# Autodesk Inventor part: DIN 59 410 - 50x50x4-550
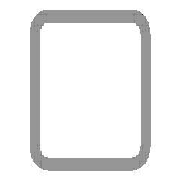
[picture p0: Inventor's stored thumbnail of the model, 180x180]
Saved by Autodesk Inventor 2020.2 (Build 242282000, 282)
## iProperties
Manager: www.cadconsulting.pl
Company: Fabian Stasiak CAD Consulting
Created: 2015-01
Part Number: DIN 59 410 - 50x50x4-550
Material: Stal, miękka
Description: Rurki stalowe o przekroju kwadratowym formowane na gorąco
Document SubType Name: Modellieren
Standard: DIN
Designer: F.Stasiak
Standards Organization: DIN
Language: pl-PL
Size Designation: 50x50x4
Categories: <MemberInstance><Categories><Category DisplayName="Kształtowniki konstrukcyjne" InternalName="089c4875-fa83-4c05-b084-43b9cc11f5ed" Mnemonic="GRDR"><CategoryPar
Stock Number: 50x50x4
Density: 7.85 g/cm^3
Appearance: Częściowo polerowana
Mass: 2999.78 g
Surface Area: 1924.59 cm^2
Volume: 382.138 cm^3
Catalog Web Link: www.expertbooks.pl
_CCFamilyMember: 40
_CCFamilyDisplayName: DIN 59410 (Kwadrat) - Rurki stalowe o przekroju kwadratowym formowane na gorąco
_FrameMemberDoc: Frame Member File
_Version: 15.0.0
_GetPNFromCC: 1
G_W: 50,000 mm
G_H: 50,000 mm
+771D13C0-1A38-4208-AF17-24ABC22D7A5B+CUTDETAIL1: Wytnij
+347A34AB-5A00-467B-B15B-B8A7DB2C3569+CUTDETAIL2: Wytnij
G_L: 550,000 mm
IsCustomPart: 1
Author: F.Stasiak
Subject: Zbiór ćwiczeń. Autodesk Inventor 2020. Kurs Professional
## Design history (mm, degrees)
node "Płaszczyzna początkowa"
node "Płaszczyzna końcowa"
sketch "Szkic"
  geometry: L1 (-17, 25)-(17, 25); L2 (25, 17)-(25, -17); L3 (17, -25)-(-17, -25); L4 (-25, -17)-(-25, 17); L5 (-37.32, 0)-(37.32, 0) reference; L6 (0, -37.32)-(0, 37.32) reference; L7 (-17, 21)-(17, 21); L8 (21, 17)-(21, -17); L9 (17, -21)-(-17, -21); L10 (-21, -17)-(-21, 17); A1 r 8 centre (-17, 17) between (-17, 25) and (-25, 17); A2 r 8 centre (17, 17) between (25, 17) and (17, 25); A3 r 8 centre (17, -17) between (17, -25) and (25, -17); A4 r 8 centre (-17, -17) between (-25, -17) and (-17, -25); A5 r 4 centre (-17, 17) between (-17, 21) and (-21, 17); A6 r 4 centre (17, 17) between (21, 17) and (17, 21); A7 r 4 centre (17, -17) between (17, -21) and (21, -17); A8 r 4 centre (-17, -17) between (-21, -17) and (-17, -21); 3 further points
  constraints: 16 end point, 16 point on circle, 8 centre point, 8 tangent, 6 point on line, 4 parallel, 3 equal radius, 3 perpendicular, 1 horizontal, 7 other
  dimensions: "b" = 50 distance of point (-25, 25) point (25, 25); "msp_r" = 8 radius of A1 (= 2 x ParT); "d8" = 25 distance between parallel lines of L4 L6 (= d9); "d9" = 25 distance between parallel lines of L3 L5 (= 0.5 x b); "d10" = 4 distance between parallel lines of L3 L9 (= ParT)
extrude "Bryła" new body sketch "Szkic" taper "d4" = 0 deg; stored distance "NLG" = 10
node "Driven Length"
  sketch "Sketch2"
    geometry: L1 (0, 0)-(10, 0) reference
    constraints: 2 end point, 1 horizontal
  workplane "Work Plane3"
  sketch "Sketch3"
    geometry: L1 (-2, 25)-(12, 25) reference; L2 (-2, 575)-(12, 575) reference
    dimensions: "d14" = 550 distance between parallel lines of L1 L2 (derived)
node "Płaszczyzna konstrukcyjna4"
feature "Podział1"
node "Płaszczyzna konstrukcyjna5"
feature "Podział2"
body "Solid1"
other parameters: "ParT" = 4, "G_OFFSET_START" = -25 [user parameter; used in 1 equation term], "G_OFFSET_END" = -25 [user parameter; used in 1 equation term], "d11" = 25 (= -G_OFFSET_START), "d12" = 575 (= G_OFFSET_END + B_L), "G_L" = 550 (= d14) [user parameter], "d13" = 90 deg
